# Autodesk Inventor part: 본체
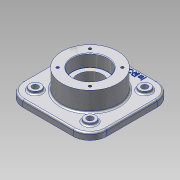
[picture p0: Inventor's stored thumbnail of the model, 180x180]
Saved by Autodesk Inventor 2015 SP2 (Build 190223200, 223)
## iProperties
Created: 2015-07
Part Number: 본체
Material: 일반
Document SubType Name: Modeling
Designer: AMC
Density: 1 g/cm^3
Appearance: 알루미늄 - 평지
Author: AMC
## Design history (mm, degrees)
sketch "스케치1"
  geometry: L1 (-75, -75)-(75, -75); L2 (75, -75)-(75, 75); L3 (75, 75)-(-75, 75); L4 (-75, 75)-(-75, -75); L5 (-75, -75)-(75, 75); L6 (75, -75)-(-75, 75); 1 further point
  constraints: 12 end point, 2 midpoint, 2 parallel, 1 horizontal, 1 perpendicular
  dimensions: "d0" = 150 distance of L3.end L2.end; "d1" = 150 distance of L2.end L1.end
extrude "돌출1" new body sketch "스케치1" distance "d2" = 12; taper "d3" = 0 deg
sketch "스케치2"
  geometry: C1 r 50 at (0, 0); 1 further point
  constraints: 1 centre point, 1 coincident
  dimensions: "d4" = 100 diameter of C1
extrude "돌출2" join sketch "스케치2" distance "d5" = 35; taper "d7" = 0 deg; dims "d6" = 35, "d8" = 0
sketch "스케치3"
  geometry: L1 (-75, 75)-(-75, -75) reference; L2 (75, 75)-(-75, 75) reference; C1 r 10 at (-49, 49); C2 r 10 at (49, 49); C3 r 10 at (-49, -49); C4 r 10 at (49, -49); 1 further point
  constraints: 4 centre point
  dimensions: "d9" = 20 diameter of C1; "d10" = 20 diameter of C2; "d11" = 20 diameter of C3; "d12" = 20 diameter of C4; "d13" = 26 distance from line of L1 C1.centre; "d14" = 26 distance from line of C1.centre L2; "d15" = 98 distance of C3.centre C1.centre; "d16" = 98 distance of C2.centre C1.centre; "d17" = 98 distance of C4.centre C2.centre; "d18" = 98 distance of C4.centre C3.centre; "d19" = 26 distance from line of L2 C2.centre; "d20" = 26 distance from line of L1 C3.centre
extrude "돌출3" join sketch "스케치3" distance "d21" = 5; taper "d22" = 0 deg
hole "구멍1" diameter "d25" = 11; stored, may be unused: countersink angle "d29" = 90 deg, drill point angle "d31" = 118 deg; dims "d23" = 10, "d24" = 10, "d26" = 6, "d27" = 4, "d28" = 2, "d30" = 8
hole "구멍2" diameter "d34" = 11; stored, may be unused: countersink angle "d38" = 90 deg, drill point angle "d40" = 118 deg; dims "d32" = 10, "d33" = 10, "d35" = 6, "d36" = 4, "d37" = 2, "d39" = 8
hole "구멍3" diameter "d43" = 11; stored, may be unused: countersink angle "d47" = 90 deg, drill point angle "d49" = 118 deg; dims "d41" = 10, "d42" = 10, "d44" = 6, "d45" = 4, "d46" = 2, "d48" = 8
hole "구멍4" diameter "d52" = 11; stored, may be unused: countersink angle "d56" = 90 deg, drill point angle "d58" = 118 deg; dims "d50" = 10, "d51" = 10, "d53" = 6, "d54" = 4, "d55" = 2, "d57" = 8
hole "구멍5" diameter "d61" = 62; stored, may be unused: countersink angle "d65" = 90 deg, drill point angle "d67" = 0 deg; dims "d59" = 10, "d60" = 10, "d62" = 6, "d63" = 4, "d64" = 2, "d66" = 22
hole "구멍6" diameter "d70" = 45; stored, may be unused: countersink angle "d74" = 90 deg, drill point angle "d76" = 0 deg; dims "d68" = 10, "d69" = 10, "d71" = 6, "d72" = 64, "d73" = 22, "d75" = 22
sketch "스케치4"
  geometry: L1 (0, 0)-(41, 0); L2 (0, 0)-(28.991, 28.991); A1 r 41 centre (0, 0) between (41, 0) and (28.991, 28.991); 1 further point
  constraints: 4 end point, 2 point on circle, 1 centre point, 1 coincident, 1 horizontal
  dimensions: "d77" = 82 diameter of A1; "d78" = 45 deg angle of L1 L2
hole "구멍7" sketch "스케치4" at (28.991, 28.991) diameter "d79" = 4.917; stored, may be unused: countersink angle "d83" = 90 deg, drill point angle "d85" = 118 deg; dims "d80" = 10, "d81" = 64, "d82" = 22, "d84" = 13
sketch "스케치5"
  geometry: L1 (0, 0)-(41, 0); L2 (0, 0)-(28.991, 28.991); A1 r 41 centre (0, 0) between (41, 0) and (28.991, 28.991); 1 further point
  constraints: 4 end point, 2 point on circle, 1 centre point, 1 coincident, 1 horizontal
  dimensions: "d89" = 82 diameter of A1; "d90" = 45 deg angle of L1 L2
hole "구멍8" sketch "스케치5" at (28.991, 28.991) diameter "d91" = 4.917; stored, may be unused: countersink angle "d95" = 90 deg, drill point angle "d97" = 118 deg; dims "d92" = 10, "d93" = 64, "d94" = 22, "d96" = 13
fillet "모깎기1" dims "d101" = 30
fillet "모깎기2" dims "d102" = 3
fillet "모깎기3" dims "d103" = 0.3
chamfer "모따기1" distance "d104" = 1; stored, may be unused: second distance "d105" = 2, angle "d106" = 45 deg
chamfer "모따기2" distance "d107" = 1; stored, may be unused: second distance "d108" = 2, angle "d109" = 45 deg
sketch "스케치6"
  geometry: 2 further points
  constraints: 1 vertical alignment, 1 other
  dimensions: "d110" = 65 distance of point (0, 0) point (0, 65)
feature "엠보싱1" sketch "스케치6" dims "d0" = 150, "d1" = 150, "d9" = 20, "d10" = 20, "d11" = 20, "d12" = 20, "d13" = 26, "d14" = 26, "d15" = 98, "d16" = 98, "d17" = 98, "d18" = 98, "d19" = 26, "d20" = 26, "d111" = 1, "d112" = 0
fillet "모깎기4" dims "d113" = 3
node "솔리드1"
pattern_circular "원형 패턴1" dims angle "d87" = 360 deg
pattern_circular "원형 패턴2" dims angle "d99" = 360 deg
